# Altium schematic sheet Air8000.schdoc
size 601 x 429 mm; Symbol: Drawing-Symbol_A2; Device: Drawing-Symbol_A2; Company: 嘉立创EDA; Version: V1.0; Page Size: A2; @Project Name: 8000; @Page Count: 1; @Update Date: 2025-03-21; @Create Date: 2025-03-21; @Schematic Name: Schematic1; @Page No: 1; @Page Name: P1; @Create Time: 08:01:54; @Update Time: 16:01:54; Width: 2338; Height: 1652; Region Start: 1; X Region Count: 6; Y Region Count: 4; Blade Width: 10; Title Block Position: 3; @Board Name: PCB7
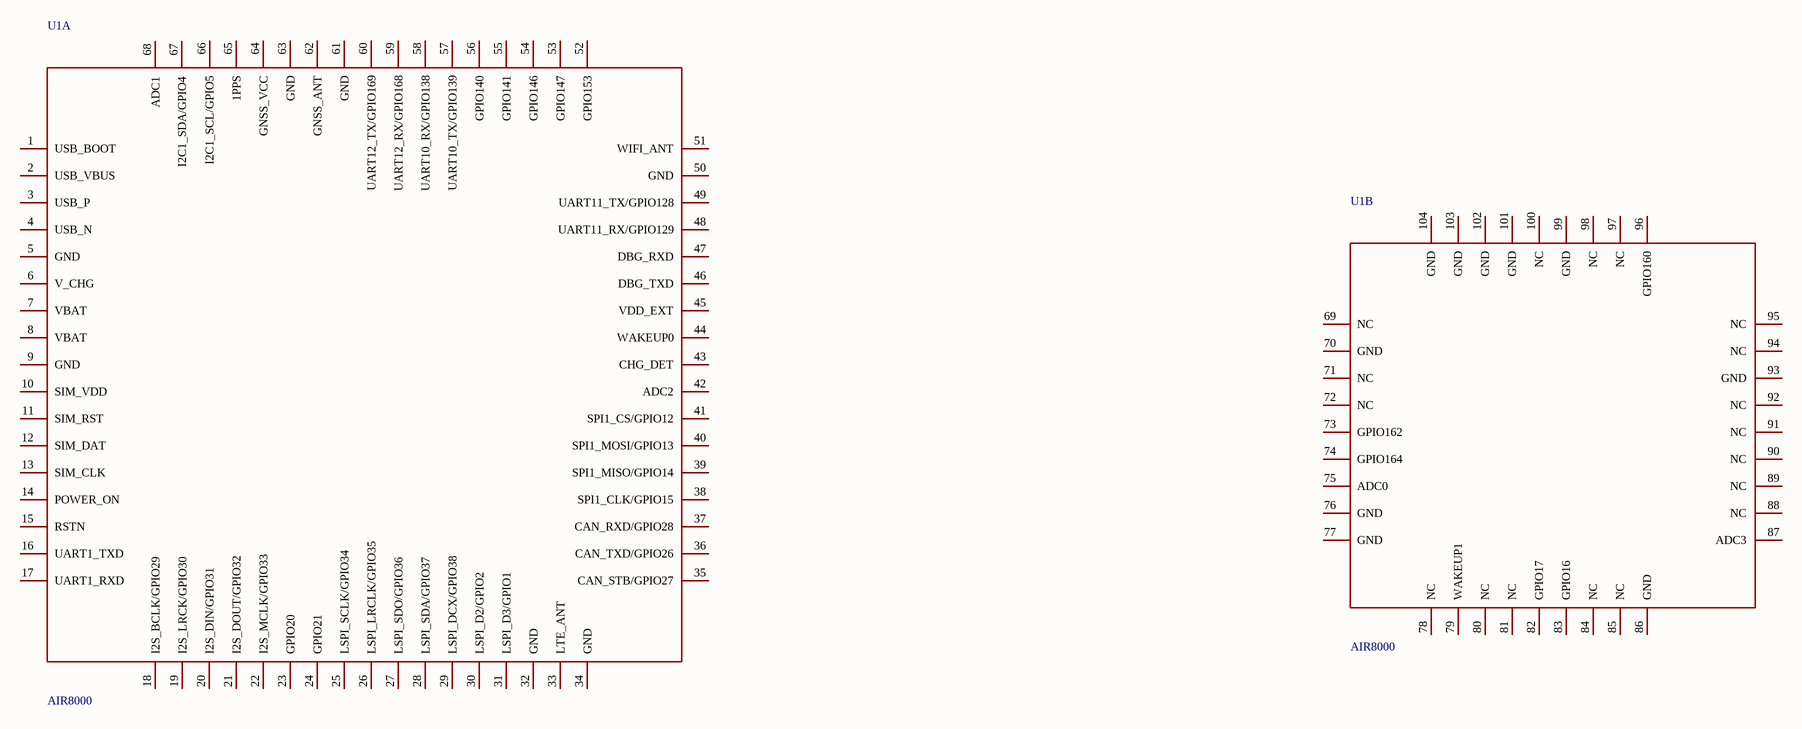
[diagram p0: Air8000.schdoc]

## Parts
U1  AIR8000  [AIR8000-PADS]  (parts A,B of 2)

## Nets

Not connected (* = marked no-connect by the designer): U1 1(USB_BOOT) 2(USB_VBUS) 3(USB_P) 4(USB_N) 5(GND) 6(V_CHG) 7(VBAT) 8(VBAT) 9(GND) 10(SIM_VDD) 11(SIM_RST) 12(SIM_DAT) 13(SIM_CLK) 14(POWER_ON) 15(RSTN) 16(UART1_TXD) 17(UART1_RXD) 18(I2S_BCLK/GPIO29) 19(I2S_LRCK/GPIO30) 20(I2S_DIN/GPIO31) 21(I2S_DOUT/GPIO32) 22(I2S_MCLK/GPIO33) 23(GPIO20) 24(GPIO21) 25(LSPI_SCLK/GPIO34) 26(LSPI_LRCLK/GPIO35) 27(LSPI_SDO/GPIO36) 28(LSPI_SDA/GPIO37) 29(LSPI_DCX/GPIO38) 30(LSPI_D2/GPIO2) 31(LSPI_D3/GPIO1) 32(GND) 33(LTE_ANT) 34(GND) 35(CAN_STB/GPIO27) 36(CAN_TXD/GPIO26) 37(CAN_RXD/GPIO28) 38(SPI1_CLK/GPIO15) 39(SPI1_MISO/GPIO14) 40(SPI1_MOSI/GPIO13) 41(SPI1_CS/GPIO12) 42(ADC2) 43(CHG_DET) 44(WAKEUP0) 45(VDD_EXT) 46(DBG_TXD) 47(DBG_RXD) 48(UART11_RX/GPIO129) 49(UART11_TX/GPIO128) 50(GND) 51(WIFI_ANT) 52(GPIO153) 53(GPIO147) 54(GPIO146) 55(GPIO141) 56(GPIO140) 57(UART10_TX/GPIO139) 58(UART10_RX/GPIO138) 59(UART12_RX/GPIO168) 60(UART12_TX/GPIO169) 61(GND) 62(GNSS_ANT) 63(GND) 64(GNSS_VCC) 65(1PPS) 66(I2C1_SCL/GPIO5) 67(I2C1_SDA/GPIO4) 68(ADC1) 69(NC) 70(GND) 71(NC) 72(NC) 73(GPIO162) 74(GPIO164) 75(ADC0) 76(GND) 77(GND) 78(NC) 79(WAKEUP1) 80(NC) 81(NC) 82(GPIO17) 83(GPIO16) 84(NC) 85(NC) 86(GND) 87(ADC3) 88(NC) 89(NC) 90(NC) 91(NC) 92(NC) 93(GND) 94(NC) 95(NC) 96(GPIO160) 97(NC) 98(NC) 99(GND) 100(NC) 101(GND) 102(GND) 103(GND) 104(GND)

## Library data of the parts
U1 = AIR8000: Add into BOM: yes; Relevance: []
